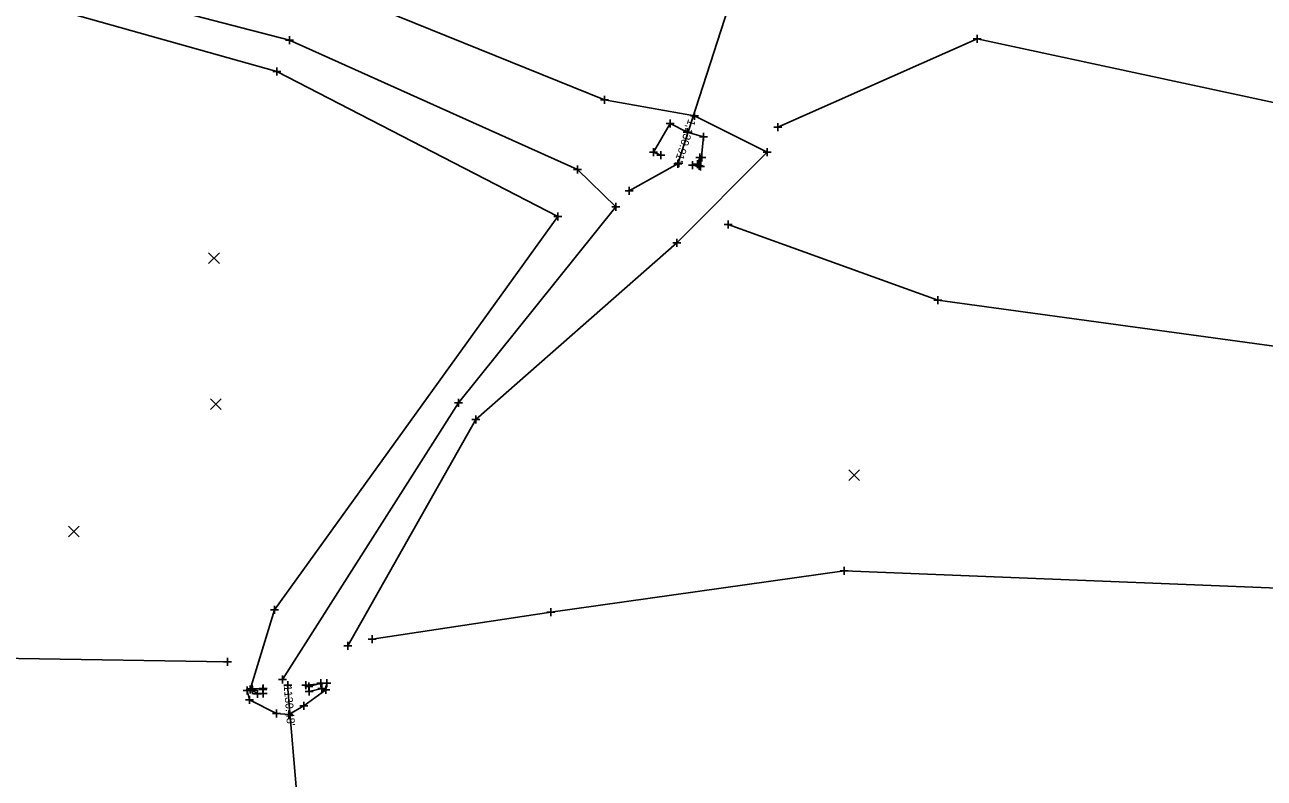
# Model space of a CAD drawing. Extents: x 207090 to 277928, y 600777 to 621109.
# Drawn here: x 261514.5 to 261669.3, y 612367.8 to 612461.9 of the extents above; entities that cross this region are included whole.
import ezdxf

# ---------------------------------------------------------------- set-up
doc = ezdxf.new("R2010")
doc.units = 0
for name, color, linetype in [('ATDIMS', 7, 'Continuous'), ('BR_X_SV_Abut', 7, 'Continuous'), ('DR_X_Ditch', 7, 'Continuous'), ('DR_X_Headwall', 7, 'Continuous'), ('DR_X_Storm_Sewer', 7, 'Continuous'), ('PM_P_Edge_Line', 7, 'Continuous'), ('PM_P_Stop_Line', 7, 'Continuous'), ('PM_X_Edge_Line', 7, 'Continuous'), ('SC_ProfileRun2', 7, 'Continuous'), ('SV_X_Break_Lines', 7, 'Continuous'), ('SV_X_Toe_of_Slope', 7, 'Continuous')]:
    doc.layers.add(name, color=color, linetype=linetype)

msp = doc.modelspace()

# ---------------------------------------------------------------- linework, layer by layer
at = {"layer": 'BR_X_SV_Abut'}
msp.add_lwpolyline([(261598.74, 612444.32), (261599.08, 612445.37), (261598.83, 612445.36), (261598.54, 612444.52)], dxfattribs=at)
at = {"layer": 'DR_X_Ditch'}
for points in [[(261268.39, 612538.37), (261322.21, 612533.48), (261359.37, 612527.32), (261409.27, 612506.67), (261456.01, 612488.51), (261506.18, 612470.76), (261547.55, 612460), (261583.55, 612443.86), (261588.32, 612439.17), (261568.67, 612414.68), (261546.67, 612380.14)], [(261596.19, 612444.66), (261589.99, 612441.18)]]:
    msp.add_lwpolyline(points, dxfattribs=at)
at = {"layer": 'DR_X_Headwall'}
for points in [[(261544.24, 612378.86), (261544.27, 612378.36), (261543.57, 612378.32), (261542.93, 612378.8)], [(261549.98, 612379.24), (261551.46, 612379.66), (261551.59, 612378.99), (261550.01, 612378.62)]]:
    msp.add_lwpolyline(points, dxfattribs=at)
at = {"layer": 'DR_X_Storm_Sewer'}
for p, q in [((261630.86, 612552.46), (261596.09, 612444.54)), ((261547.33, 612379.42), (261572.44, 612081.43))]:
    msp.add_line(p, q, dxfattribs=at)
at = {"layer": 'PM_P_Edge_Line'}
for points in [[(261263.47, 612539.83), (261269.01, 612541.34), (261322.02, 612535.23), (261361.19, 612530.5), (261411.17, 612512.95), (261459.12, 612494.16), (261509.03, 612478.25), (261549.54, 612467.7), (261586.92, 612452.56), (261598.14, 612450.56), (261607.22, 612446.03), (261595.95, 612434.69), (261570.84, 612412.62), (261554.87, 612384.32)], [(261263.33, 612539.26), (261268.28, 612536.81), (261321.23, 612530.7), (261357.06, 612521.5), (261408.09, 612502.78), (261453.99, 612483.63), (261504.43, 612467.79), (261545.99, 612456.09), (261581.09, 612437.96), (261545.67, 612388.85), (261542.67, 612378.86)], [(261903.19, 612388.16), (261853.85, 612396.6), (261799.07, 612414.09), (261746.75, 612428.59), (261686.18, 612448.84), (261633.46, 612460.17), (261608.58, 612449.13)]]:
    msp.add_lwpolyline(points, dxfattribs=at)
at = {"layer": 'PM_P_Stop_Line'}
for p, q in [((261633.46, 612460.67), (261633.46, 612459.67)), ((261547.05, 612460), (261548.05, 612460)), ((261547.55, 612460.5), (261547.55, 612459.5)), ((261547.55, 612460), (261547.55, 612460)), ((261632.96, 612460.17), (261633.96, 612460.17)), ((261633.46, 612460.17), (261633.46, 612460.17)), ((261545.49, 612456.09), (261546.49, 612456.09)), ((261545.99, 612456.59), (261545.99, 612455.59)), ((261545.99, 612456.09), (261545.99, 612456.09)), ((261586.92, 612453.06), (261586.92, 612452.06)), ((261586.42, 612452.56), (261587.42, 612452.56)), ((261586.92, 612452.56), (261586.92, 612452.56)), ((261595.12, 612450.1), (261595.12, 612449.1)), ((261597.64, 612450.56), (261598.64, 612450.56)), ((261598.14, 612451.06), (261598.14, 612450.06)), ((261598.14, 612450.56), (261598.14, 612450.56)), ((261594.62, 612449.6), (261595.62, 612449.6)), ((261595.12, 612449.6), (261595.12, 612449.6)), ((261596.73, 612448.53), (261597.73, 612448.53)), ((261597.23, 612449.03), (261597.23, 612448.03)), ((261597.23, 612448.53), (261597.23, 612448.53)), ((261599.29, 612448.43), (261599.29, 612447.43)), ((261608.08, 612449.13), (261609.08, 612449.13)), ((261608.58, 612449.63), (261608.58, 612448.63)), ((261608.58, 612449.13), (261608.58, 612449.13)), ((261598.79, 612447.93), (261599.79, 612447.93)), ((261599.29, 612447.93), (261599.29, 612447.93)), ((261592.52, 612446), (261593.52, 612446)), ((261593.02, 612446.5), (261593.02, 612445.5)), ((261593.02, 612446), (261593.02, 612446)), ((261593.43, 612445.64), (261594.43, 612445.64)), ((261593.93, 612446.14), (261593.93, 612445.14)), ((261593.93, 612445.64), (261593.93, 612445.64)), ((261596.19, 612445.16), (261596.19, 612444.16)), ((261598.33, 612445.36), (261599.33, 612445.36)), ((261598.58, 612445.37), (261599.58, 612445.37)), ((261598.83, 612445.86), (261598.83, 612444.86)), ((261598.83, 612445.36), (261598.83, 612445.36)), ((261599.08, 612445.87), (261599.08, 612444.87)), ((261599.08, 612445.37), (261599.08, 612445.37)), ((261606.72, 612446.03), (261607.72, 612446.03)), ((261607.22, 612446.53), (261607.22, 612445.53)), ((261607.22, 612446.03), (261607.22, 612446.03)), ((261583.05, 612443.86), (261584.05, 612443.86)), ((261583.55, 612444.36), (261583.55, 612443.36)), ((261583.55, 612443.86), (261583.55, 612443.86)), ((261595.69, 612444.66), (261596.69, 612444.66)), ((261596.19, 612444.66), (261596.19, 612444.66)), ((261597.4, 612444.38), (261598.4, 612444.38)), ((261597.9, 612444.88), (261597.9, 612443.88)), ((261597.9, 612444.38), (261597.9, 612444.38)), ((261598.04, 612444.52), (261599.04, 612444.52)), ((261598.24, 612444.32), (261599.24, 612444.32)), ((261598.39, 612444.21), (261599.39, 612444.21)), ((261598.54, 612445.02), (261598.54, 612444.02)), ((261598.54, 612444.52), (261598.54, 612444.52)), ((261598.74, 612444.82), (261598.74, 612443.82)), ((261598.74, 612444.32), (261598.74, 612444.32)), ((261598.89, 612444.71), (261598.89, 612443.71)), ((261598.89, 612444.21), (261598.89, 612444.21)), ((261589.49, 612441.18), (261590.49, 612441.18)), ((261589.99, 612441.68), (261589.99, 612440.68)), ((261589.99, 612441.18), (261589.99, 612441.18)), ((261587.82, 612439.17), (261588.82, 612439.17)), ((261588.32, 612439.67), (261588.32, 612438.67)), ((261588.32, 612439.17), (261588.32, 612439.17)), ((261580.59, 612437.96), (261581.59, 612437.96)), ((261581.09, 612438.46), (261581.09, 612437.46)), ((261581.09, 612437.96), (261581.09, 612437.96)), ((261602.35, 612437.48), (261602.35, 612436.48)), ((261601.85, 612436.98), (261602.85, 612436.98)), ((261602.35, 612436.98), (261602.35, 612436.98)), ((261595.45, 612434.69), (261596.45, 612434.69)), ((261595.95, 612435.19), (261595.95, 612434.19)), ((261595.95, 612434.69), (261595.95, 612434.69)), ((261628.06, 612427.54), (261629.06, 612427.54)), ((261628.56, 612428.04), (261628.56, 612427.04)), ((261628.56, 612427.54), (261628.56, 612427.54)), ((261568.17, 612414.68), (261569.17, 612414.68)), ((261568.67, 612415.18), (261568.67, 612414.18)), ((261568.67, 612414.68), (261568.67, 612414.68)), ((261570.34, 612412.62), (261571.34, 612412.62)), ((261570.84, 612413.12), (261570.84, 612412.12)), ((261570.84, 612412.62), (261570.84, 612412.62)), ((261616.83, 612394.2), (261616.83, 612393.2)), ((261616.33, 612393.7), (261617.33, 612393.7)), ((261616.83, 612393.7), (261616.83, 612393.7)), ((261545.67, 612389.35), (261545.67, 612388.35)), ((261545.17, 612388.85), (261546.17, 612388.85)), ((261545.67, 612388.85), (261545.67, 612388.85)), ((261579.71, 612388.52), (261580.71, 612388.52)), ((261580.21, 612389.02), (261580.21, 612388.02)), ((261580.21, 612388.52), (261580.21, 612388.52)), ((261554.87, 612384.82), (261554.87, 612383.82)), ((261557.38, 612385.17), (261558.38, 612385.17)), ((261557.88, 612385.67), (261557.88, 612384.67)), ((261557.88, 612385.17), (261557.88, 612385.17)), ((261554.37, 612384.32), (261555.37, 612384.32)), ((261554.87, 612384.32), (261554.87, 612384.32)), ((261539.3, 612382.34), (261540.3, 612382.34)), ((261539.8, 612382.84), (261539.8, 612381.84)), ((261539.8, 612382.34), (261539.8, 612382.34)), ((261546.17, 612380.14), (261547.17, 612380.14)), ((261546.67, 612380.64), (261546.67, 612379.64)), ((261546.67, 612380.14), (261546.67, 612380.14)), ((261551.46, 612380.16), (261551.46, 612379.16)), ((261552.22, 612380.18), (261552.22, 612379.18)), ((261541.78, 612378.76), (261542.78, 612378.76)), ((261542.17, 612378.86), (261543.17, 612378.86)), ((261542.28, 612379.26), (261542.28, 612378.26)), ((261542.28, 612378.76), (261542.28, 612378.76)), ((261542.41, 612378.96), (261543.41, 612378.96)), ((261542.43, 612378.8), (261543.43, 612378.8)), ((261542.67, 612379.36), (261542.67, 612378.36)), ((261542.67, 612378.86), (261542.67, 612378.86)), ((261542.91, 612379.46), (261542.91, 612378.46)), ((261542.91, 612378.96), (261542.91, 612378.96)), ((261542.93, 612379.3), (261542.93, 612378.3)), ((261542.93, 612378.8), (261542.93, 612378.8)), ((261543.57, 612378.82), (261543.57, 612377.82)), ((261543.74, 612378.86), (261544.74, 612378.86)), ((261543.78, 612379.01), (261544.78, 612379.01)), ((261544.24, 612379.36), (261544.24, 612378.36)), ((261544.24, 612378.86), (261544.24, 612378.86)), ((261544.27, 612378.86), (261544.27, 612377.86)), ((261544.28, 612379.51), (261544.28, 612378.51)), ((261544.28, 612379.01), (261544.28, 612379.01)), ((261549.12, 612379.42), (261550.12, 612379.42)), ((261549.48, 612379.24), (261550.48, 612379.24)), ((261549.51, 612378.62), (261550.51, 612378.62)), ((261549.62, 612379.92), (261549.62, 612378.92)), ((261549.62, 612379.42), (261549.62, 612379.42)), ((261549.98, 612379.74), (261549.98, 612378.74)), ((261549.98, 612379.24), (261549.98, 612379.24)), ((261550.01, 612379.12), (261550.01, 612378.12)), ((261550.01, 612378.62), (261550.01, 612378.62)), ((261550.96, 612379.66), (261551.96, 612379.66)), ((261551.09, 612378.99), (261552.09, 612378.99)), ((261551.46, 612379.66), (261551.46, 612379.66)), ((261551.59, 612379.49), (261551.59, 612378.49)), ((261551.59, 612378.99), (261551.59, 612378.99)), ((261551.62, 612378.85), (261552.62, 612378.85)), ((261551.72, 612379.68), (261552.72, 612379.68)), ((261552.12, 612379.35), (261552.12, 612378.35)), ((261552.12, 612378.85), (261552.12, 612378.85)), ((261552.22, 612379.68), (261552.22, 612379.68)), ((261542.08, 612377.58), (261543.08, 612377.58)), ((261542.58, 612378.08), (261542.58, 612377.08)), ((261542.58, 612377.58), (261542.58, 612377.58)), ((261543.07, 612378.32), (261544.07, 612378.32)), ((261543.57, 612378.32), (261543.57, 612378.32)), ((261543.77, 612378.36), (261544.77, 612378.36)), ((261544.27, 612378.36), (261544.27, 612378.36)), ((261549.35, 612377.34), (261549.35, 612376.34)), ((261545.45, 612375.89), (261546.45, 612375.89)), ((261545.95, 612376.39), (261545.95, 612375.39)), ((261545.95, 612375.89), (261545.95, 612375.89)), ((261546.97, 612375.77), (261547.97, 612375.77)), ((261547.47, 612376.27), (261547.47, 612375.27)), ((261547.47, 612375.77), (261547.47, 612375.77)), ((261548.85, 612376.84), (261549.85, 612376.84)), ((261549.35, 612376.84), (261549.35, 612376.84))]:
    msp.add_line(p, q, dxfattribs=at)
at = {"layer": 'PM_X_Edge_Line'}
for p, q in [((261537.46, 612432.09), (261538.8, 612433.43)), ((261537.46, 612433.43), (261538.8, 612432.09)), ((261537.69, 612413.88), (261539.02, 612415.21)), ((261537.69, 612415.21), (261539.02, 612413.88)), ((261617.44, 612404.99), (261618.77, 612406.33)), ((261617.44, 612406.33), (261618.77, 612404.99)), ((261519.94, 612397.97), (261521.28, 612399.3)), ((261519.94, 612399.3), (261521.28, 612397.97))]:
    msp.add_line(p, q, dxfattribs=at)
at = {"layer": 'SC_ProfileRun2'}
for p, q in [((261595.59, 612444.55), (261596.59, 612444.55)), ((261596.09, 612445.05), (261596.09, 612444.05)), ((261596.09, 612444.55), (261596.09, 612444.55)), ((261546.84, 612379.42), (261547.84, 612379.42)), ((261547.34, 612379.92), (261547.34, 612378.92)), ((261547.34, 612379.42), (261547.34, 612379.42))]:
    msp.add_line(p, q, dxfattribs=at)
at = {"layer": 'SV_X_Break_Lines'}
for points in [[(261593.93, 612445.64), (261593.02, 612446), (261595.12, 612449.6), (261597.23, 612448.53), (261599.29, 612447.93), (261598.89, 612444.21), (261597.9, 612444.38)], [(261544.28, 612379.01), (261542.91, 612378.96), (261542.28, 612378.76), (261542.58, 612377.58), (261545.95, 612375.89), (261547.47, 612375.77), (261549.35, 612376.84), (261552.12, 612378.85), (261552.22, 612379.68), (261549.62, 612379.42)]]:
    msp.add_lwpolyline(points, dxfattribs=at)
at = {"layer": 'SV_X_Toe_of_Slope'}
for points in [[(261956.02, 612369.99), (261901.81, 612376.69), (261801.72, 612396.42), (261738.36, 612407.67), (261685.74, 612419.69), (261628.56, 612427.54), (261602.35, 612436.98)], [(261557.88, 612385.17), (261580.21, 612388.52), (261616.83, 612393.7), (261689.76, 612390.8), (261879.9, 612378.05)], [(261539.8, 612382.34), (261505.85, 612382.89), (261448.54, 612380.44), (261392.5, 612374.07), (261335.56, 612364.89), (261278.08, 612357.04), (261220.51, 612346.74), (261210.6, 612350.88), (261193.53, 612351.08), (261178.4, 612342.5), (261154.63, 612329.55), (261137.65, 612317.38), (261126.95, 612293.37)]]:
    msp.add_lwpolyline(points, dxfattribs=at)

# ---------------------------------------------------------------- texts
at = {"layer": 'ATDIMS'}
for s, rotation, p in [("1,130.91'", 252.1384, (261597.39, 612450.2)), ("1130.48'", 274.8155, (261546.84, 612379.38))]:
    msp.add_text(s, height=1, rotation=rotation, dxfattribs=at).set_placement(p)

doc.saveas('drawing.dxf')
